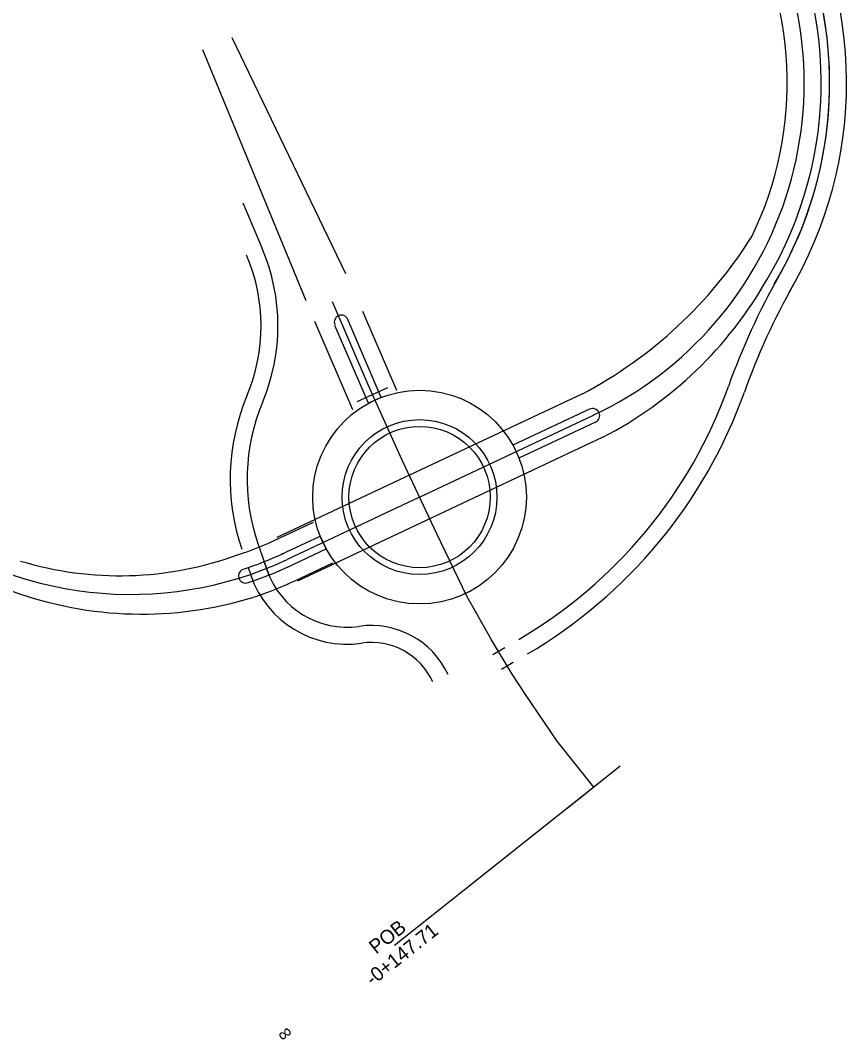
# Model space of a CAD drawing. Extents: x 0 to 513042, y 0 to 6212511.
# Drawn here: x 511756.2 to 511902.5, y 6211623.7 to 6211804 of the extents above; entities that cross this region are included whole.
import ezdxf

# ---------------------------------------------------------------- set-up
doc = ezdxf.new("R2010")
doc.units = 0
for name, color, linetype in [('Default', 7, 'Continuous'), ('TV_A_FKT_Sti--', 7, 'Continuous'), ('TV_G_KRN_ForTv', 7, 'Continuous'), ('TV_G_KRN_KBK--', 7, 'Continuous'), ('TV_G_KRN_KtStn', 7, 'Continuous'), ('TV_L_---_CL---_C', 7, 'Continuous'), ('TV_L_HOR_Cardn_T', 7, 'Continuous'), ('TV_L_HOR_Cardn_Tic', 7, 'Continuous'), ('TV_L_HOR_ElmRA_T', 7, 'Continuous'), ('TV_L_HOR_Statn_Tic', 7, 'Continuous')]:
    doc.layers.add(name, color=color, linetype=linetype)

msp = doc.modelspace()

# ---------------------------------------------------------------- linework, layer by layer
at = {"layer": 'Default'}
msp.add_circle((511826.88, 6211719.71), 12.5, dxfattribs=at)
at = {"layer": 'TV_A_FKT_Sti--'}
msp.add_line((511798.27, 6211711.48), (511799.88, 6211706.79), dxfattribs=at)
for centre, radius, start, end in [((511829.95, 6211793), 72.5, 329.1871, 31.4553), ((511829.95, 6211793), 69.5, 329.1871, 31.4553), ((511829.95, 6211793), 69.5, 330.5019, 31.4553), ((511766.82, 6211750), 35, 337.208, 23.03), ((511766.82, 6211750), 32, 337.208, 23.03), ((511999.24, 6211697.22), 125, 150.5019, 160.3369), ((511999.24, 6211697.22), 122, 150.5019, 160.3369), ((511801.49, 6211767.89), 85, 300.353, 340.3369), ((511831.36, 6211722.88), 38, 157.208, 199.0235), ((511801.49, 6211767.89), 88, 300.353, 340.3369), ((511831.36, 6211722.88), 35, 157.208, 199.0235), ((511814.06, 6211711.68), 18, 199.0235, 278.1748), ((511814.06, 6211711.68), 15, 199.0235, 278.1748), ((511818.33, 6211681.99), 15, 24.9384, 98.1748), ((511818.33, 6211681.99), 12, 24.9384, 98.1748)]:
    msp.add_arc(centre, radius, start, end, dxfattribs=at)
at = {"layer": 'TV_G_KRN_ForTv'}
for p, q in [((511795.61, 6211771.74), (511799.03, 6211763.69)), ((511817.79, 6211739.56), (511811.48, 6211754.27)), ((511823.82, 6211726.21), (511817.79, 6211739.56)), ((511826.88, 6211719.71), (511857.63, 6211734.18)), ((511829.94, 6211713.21), (511823.82, 6211726.21)), ((511826.88, 6211719.71), (511803.45, 6211708.69)), ((511835.22, 6211702.2), (511829.94, 6211713.21)), ((511839.62, 6211694.45), (511835.22, 6211702.2)), ((511843.25, 6211688.41), (511839.62, 6211694.45)), ((511845.61, 6211684.77), (511843.25, 6211688.41)), ((511851.24, 6211676.53), (511845.61, 6211684.77)), ((511857.69, 6211668.42), (511851.24, 6211676.53))]:
    msp.add_line(p, q, dxfattribs=at)
at = {"layer": 'TV_G_KRN_KBK--'}
for p, q in [((511793.64, 6211801.03), (511813.77, 6211759.28)), ((511806.81, 6211754.45), (511788.53, 6211798.84)), ((511822.85, 6211738.54), (511816.84, 6211752.54)), ((511815.07, 6211735.12), (511808.36, 6211750.75)), ((511855.7, 6211737.97), (511801.64, 6211712.53)), ((511859.31, 6211730.28), (511805.26, 6211704.84)), ((511801.28, 6211712.09), (511808.11, 6211715.3)), ((511804.69, 6211704.85), (511811.52, 6211708.06))]:
    msp.add_line(p, q, dxfattribs=at)
for radius in [18.9, 13.7]:
    msp.add_circle((511826.88, 6211719.71), radius, dxfattribs=at)
for centre, radius, start, end in [((511829.95, 6211793), 68, 329.1871, 31.4553), ((511829.95, 6211793), 62, 334.0033, 31.4553), ((511819.05, 6211807.49), 78.58, 297.7947, 327.9799), ((511826.61, 6211793.4), 71.09, 297.389, 330.2878), ((511775.78, 6211767.5), 61, 288.0205, 295.1994), ((511773.81, 6211766.22), 60.43, 253.0956, 290.1717), ((511775.78, 6211767.5), 69, 288.2609, 295.1994), ((511777.74, 6211765.7), 66.69, 249.8892, 287.1459)]:
    msp.add_arc(centre, radius, start, end, dxfattribs=at)
at = {"layer": 'TV_G_KRN_KtStn'}
for p, q in [((511820.1, 6211737.35), (511814.18, 6211751.14)), ((511817.83, 6211736.3), (511811.91, 6211750.09)), ((511820.1, 6211737.35), (511817.83, 6211736.3)), ((511856.97, 6211735.25), (511843.41, 6211728.87)), ((511858.04, 6211732.99), (511844.47, 6211726.61)), ((511802.45, 6211709.6), (511809.28, 6211712.81)), ((511809.28, 6211712.81), (511810.34, 6211710.55)), ((511803.52, 6211707.34), (511810.34, 6211710.55)), ((511796.56, 6211707.23), (511797.37, 6211704.87)), ((511799.39, 6211708.21), (511800.21, 6211705.85)), ((511833.88, 6211702.16), (511836.09, 6211703.21)), ((511839.84, 6211691.84), (511841.94, 6211693.08)), ((511841.35, 6211689.25), (511843.46, 6211690.49))]:
    msp.add_line(p, q, dxfattribs=at)
for centre, radius, start, end in [((511813.03, 6211750.65), 1.25, 23.2287, 203.2287), ((511857.5, 6211734.12), 1.25, 294.2128, 114.2128), ((511775.78, 6211767.5), 63.75, 288.0205, 295.1994), ((511796.1, 6211705.77), 1.26, 118.6394, 290.0935), ((511775.78, 6211767.5), 66.25, 288.2609, 295.1994)]:
    msp.add_arc(centre, radius, start, end, dxfattribs=at)
at = {"layer": 'TV_L_---_CL---_C'}
for centre, start, end in [((511829.95, 6211793), 295.1994, 31.4553), ((511775.78, 6211767.5), 231.9142, 295.1994)]:
    msp.add_arc(centre, 65, start, end, dxfattribs=at)
at = {"layer": 'TV_L_HOR_Cardn_Tic'}
msp.add_lwpolyline([(511857.69, 6211668.42), (511822.47, 6211640.41)], dxfattribs=at)
at = {"layer": 'TV_L_HOR_Statn_Tic'}
for points in [[(511815.83, 6211736.62), (511821.29, 6211739.09)], [(511853, 6211664.68), (511862.39, 6211672.15)]]:
    msp.add_lwpolyline(points, dxfattribs=at)

# ---------------------------------------------------------------- texts
at = {"layer": 'TV_L_HOR_Cardn_T'}
for s, p in [('POB', (511819.19, 6211638.76)), ('-0+147.71', (511818.55, 6211633.15))]:
    msp.add_text(s, height=2.5, rotation=38.4846, dxfattribs=at).set_placement(p)
at = {"layer": 'TV_L_HOR_ElmRA_T'}
msp.add_text('∞', height=2.5, rotation=38.4846, dxfattribs=at).set_placement((511802.8, 6211623.18))

doc.saveas('drawing.dxf')
